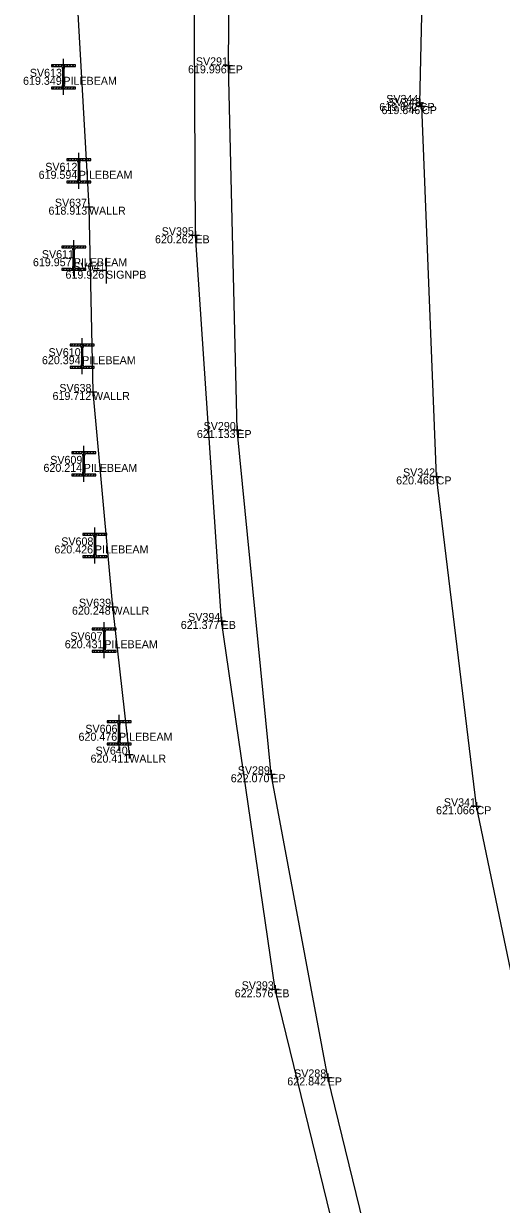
# Model space of a CAD drawing. Extents: x -2 to 1979875, y -2 to 232027.
# Drawn here: x 1978723.2 to 1978753, y 230727.4 to 230801.2 of the extents above; entities that cross this region are included whole.
import ezdxf

# ---------------------------------------------------------------- set-up
doc = ezdxf.new("R2010")
doc.units = 0
for name, color, linetype in [('_CIVIL_CONSTRUCTION', 7, 'Continuous'), ('GE_X_Alignment', 7, 'Continuous'), ('GE_X_Alignment_1000_Curve_Data', 7, 'Continuous'), ('GE_X_Alignment_1000_Stations', 7, 'Continuous'), ('GE_X_Alignment_100_Curve_Data', 7, 'Continuous'), ('GE_X_Alignment_100_Stations', 7, 'Continuous'), ('GE_X_Alignment_500_Stations', 7, 'Continuous'), ('GT_X_Piling_Cells', 7, 'Continuous'), ('RD_X_Wall', 7, 'Continuous'), ('SC_Scratch1', 7, 'Continuous')]:
    doc.layers.add(name, color=color, linetype=linetype)

msp = doc.modelspace()

# ---------------------------------------------------------------- linework, layer by layer
at = {"layer": 'GE_X_Alignment_1000_Curve_Data'}
msp.add_lwpolyline([(1978771.368, 230686.901), (1978762.945, 230707.808), (1978756.184, 230729.845), (1978751.49, 230752.309), (1978748.994, 230772.916), (1978748.08, 230796.049), (1978747.937, 230796.247), (1978748.471, 230819.071), (1978749.254, 230839.296), (1978750.532, 230861.092), (1978751.977, 230883.907), (1978753.538, 230907.259), (1978755.272, 230931.005), (1978756.708, 230952.708), (1978758.182, 230974.871), (1978759.598, 230998.872), (1978761.121, 231023.464)], dxfattribs=at)
at = {"layer": 'GE_X_Alignment_1000_Stations'}
msp.add_lwpolyline([(1978772.336, 230656.843), (1978763.559, 230673.456), (1978754.964, 230693.186), (1978747.098, 230715.323), (1978742.189, 230735.369), (1978738.656, 230754.308), (1978736.533, 230775.816), (1978735.988, 230798.596), (1978736.151, 230819.454), (1978737.13, 230840.16), (1978738.357, 230863.144), (1978739.649, 230887.098), (1978741.331, 230908.702), (1978742.827, 230930.869), (1978744.275, 230952.773), (1978745.794, 230976.041), (1978747.11, 230998.611), (1978748.464, 231019.612), (1978749.988, 231043.472)], dxfattribs=at)
at = {"layer": 'GE_X_Alignment_100_Curve_Data'}
for p, q in [((1978735.988, 230798.846), (1978735.988, 230798.346)), ((1978735.738, 230798.596), (1978736.238, 230798.596)), ((1978735.988, 230798.596), (1978735.988, 230798.596)), ((1978747.687, 230796.247), (1978748.187, 230796.247)), ((1978747.83, 230796.049), (1978748.33, 230796.049)), ((1978747.937, 230796.497), (1978747.937, 230795.997)), ((1978747.937, 230796.247), (1978747.937, 230796.247)), ((1978748.08, 230796.299), (1978748.08, 230795.799)), ((1978748.08, 230796.049), (1978748.08, 230796.049)), ((1978727.259, 230790.017), (1978727.259, 230789.517)), ((1978727.009, 230789.767), (1978727.509, 230789.767)), ((1978727.259, 230789.767), (1978727.259, 230789.767)), ((1978733.668, 230787.98), (1978734.168, 230787.98)), ((1978733.918, 230788.23), (1978733.918, 230787.73)), ((1978733.918, 230787.98), (1978733.918, 230787.98)), ((1978727.265, 230778.19), (1978727.765, 230778.19)), ((1978727.515, 230778.44), (1978727.515, 230777.94)), ((1978727.515, 230778.19), (1978727.515, 230778.19)), ((1978736.533, 230776.066), (1978736.533, 230775.566)), ((1978736.283, 230775.816), (1978736.783, 230775.816)), ((1978736.533, 230775.816), (1978736.533, 230775.816)), ((1978748.744, 230772.916), (1978749.244, 230772.916)), ((1978748.994, 230773.166), (1978748.994, 230772.666)), ((1978748.994, 230772.916), (1978748.994, 230772.916)), ((1978728.731, 230765.027), (1978728.731, 230764.527)), ((1978728.481, 230764.777), (1978728.981, 230764.777)), ((1978728.731, 230764.777), (1978728.731, 230764.777)), ((1978735.553, 230764.136), (1978735.553, 230763.636)), ((1978735.303, 230763.886), (1978735.803, 230763.886)), ((1978735.553, 230763.886), (1978735.553, 230763.886)), ((1978729.53, 230755.535), (1978730.03, 230755.535)), ((1978729.78, 230755.785), (1978729.78, 230755.285)), ((1978729.78, 230755.535), (1978729.78, 230755.535)), ((1978738.656, 230754.558), (1978738.656, 230754.058)), ((1978738.406, 230754.308), (1978738.906, 230754.308)), ((1978738.656, 230754.308), (1978738.656, 230754.308)), ((1978751.24, 230752.309), (1978751.74, 230752.309)), ((1978751.49, 230752.559), (1978751.49, 230752.059)), ((1978751.49, 230752.309), (1978751.49, 230752.309)), ((1978738.655, 230740.874), (1978739.155, 230740.874)), ((1978738.905, 230741.124), (1978738.905, 230740.624)), ((1978738.905, 230740.874), (1978738.905, 230740.874)), ((1978741.939, 230735.369), (1978742.439, 230735.369)), ((1978742.189, 230735.619), (1978742.189, 230735.119)), ((1978742.189, 230735.369), (1978742.189, 230735.369))]:
    msp.add_line(p, q, dxfattribs=at)
at = {"layer": 'GE_X_Alignment_500_Stations'}
for p, q in [((1978728.328, 230786.57), (1978728.328, 230784.97)), ((1978728.328, 230785.77), (1978727.528, 230785.77))]:
    msp.add_line(p, q, dxfattribs=at)
at = {"layer": 'GT_X_Piling_Cells'}
for p, q in [((1978725.664, 230796.755), (1978725.664, 230799.005)), ((1978726.414, 230798.63), (1978724.914, 230798.63)), ((1978724.914, 230798.63), (1978724.914, 230798.53)), ((1978724.914, 230798.53), (1978725.489, 230798.53)), ((1978724.977, 230798.53), (1978725.077, 230798.63)), ((1978725.153, 230798.53), (1978725.253, 230798.63)), ((1978725.33, 230798.53), (1978725.43, 230798.63)), ((1978725.506, 230798.529), (1978725.607, 230798.63)), ((1978725.605, 230798.451), (1978725.784, 230798.63)), ((1978725.614, 230798.405), (1978725.614, 230797.355)), ((1978725.614, 230798.284), (1978725.714, 230798.384)), ((1978725.614, 230798.107), (1978725.714, 230798.207)), ((1978725.614, 230797.93), (1978725.714, 230798.03)), ((1978725.714, 230797.355), (1978725.714, 230798.405)), ((1978725.839, 230798.53), (1978726.414, 230798.53)), ((1978725.86, 230798.53), (1978725.96, 230798.63)), ((1978726.037, 230798.53), (1978726.137, 230798.63)), ((1978726.214, 230798.53), (1978726.314, 230798.63)), ((1978726.391, 230798.53), (1978726.414, 230798.553)), ((1978726.414, 230798.53), (1978726.414, 230798.63)), ((1978725.521, 230797.13), (1978725.717, 230797.326)), ((1978725.614, 230797.753), (1978725.714, 230797.853)), ((1978725.614, 230797.576), (1978725.714, 230797.676)), ((1978725.614, 230797.4), (1978725.714, 230797.5)), ((1978725.664, 230797.88), (1978725.664, 230797.88)), ((1978725.489, 230797.23), (1978724.914, 230797.23)), ((1978724.914, 230797.23), (1978724.914, 230797.13)), ((1978724.914, 230797.13), (1978726.414, 230797.13)), ((1978724.991, 230797.13), (1978725.091, 230797.23)), ((1978725.168, 230797.13), (1978725.268, 230797.23)), ((1978725.344, 230797.13), (1978725.444, 230797.23)), ((1978725.698, 230797.13), (1978725.803, 230797.235)), ((1978726.414, 230797.23), (1978725.839, 230797.23)), ((1978725.875, 230797.13), (1978725.975, 230797.23)), ((1978726.051, 230797.13), (1978726.151, 230797.23)), ((1978726.228, 230797.13), (1978726.328, 230797.23)), ((1978726.405, 230797.13), (1978726.414, 230797.139)), ((1978726.414, 230797.13), (1978726.414, 230797.23)), ((1978726.633, 230790.882), (1978726.633, 230793.132)), ((1978727.383, 230792.757), (1978725.883, 230792.757)), ((1978725.883, 230792.757), (1978725.883, 230792.657)), ((1978725.883, 230792.657), (1978726.458, 230792.657)), ((1978725.946, 230792.657), (1978726.046, 230792.757)), ((1978726.122, 230792.657), (1978726.222, 230792.757)), ((1978726.299, 230792.657), (1978726.399, 230792.757)), ((1978726.475, 230792.656), (1978726.576, 230792.757)), ((1978726.574, 230792.578), (1978726.753, 230792.757)), ((1978726.583, 230792.532), (1978726.583, 230791.482)), ((1978726.583, 230792.411), (1978726.683, 230792.511)), ((1978726.583, 230792.234), (1978726.683, 230792.334)), ((1978726.583, 230792.057), (1978726.683, 230792.157)), ((1978726.683, 230791.482), (1978726.683, 230792.532)), ((1978726.808, 230792.657), (1978727.383, 230792.657)), ((1978726.829, 230792.657), (1978726.929, 230792.757)), ((1978727.006, 230792.657), (1978727.106, 230792.757)), ((1978727.183, 230792.657), (1978727.283, 230792.757)), ((1978727.36, 230792.657), (1978727.383, 230792.68)), ((1978727.383, 230792.657), (1978727.383, 230792.757)), ((1978726.458, 230791.357), (1978725.883, 230791.357)), ((1978725.883, 230791.357), (1978725.883, 230791.257)), ((1978725.96, 230791.257), (1978726.06, 230791.357)), ((1978726.137, 230791.257), (1978726.237, 230791.357)), ((1978726.313, 230791.257), (1978726.413, 230791.357)), ((1978726.49, 230791.257), (1978726.686, 230791.453)), ((1978726.583, 230791.88), (1978726.683, 230791.98)), ((1978726.583, 230791.703), (1978726.683, 230791.803)), ((1978726.583, 230791.527), (1978726.683, 230791.627)), ((1978726.633, 230792.007), (1978726.633, 230792.007)), ((1978726.667, 230791.257), (1978726.772, 230791.362)), ((1978727.383, 230791.357), (1978726.808, 230791.357)), ((1978726.844, 230791.257), (1978726.944, 230791.357)), ((1978727.02, 230791.257), (1978727.12, 230791.357)), ((1978727.197, 230791.257), (1978727.297, 230791.357)), ((1978727.383, 230791.257), (1978727.383, 230791.357)), ((1978725.883, 230791.257), (1978727.383, 230791.257)), ((1978727.374, 230791.257), (1978727.383, 230791.266)), ((1978726.311, 230785.423), (1978726.311, 230787.673)), ((1978727.061, 230787.298), (1978725.561, 230787.298)), ((1978725.561, 230787.298), (1978725.561, 230787.198)), ((1978725.561, 230787.198), (1978726.136, 230787.198)), ((1978725.624, 230787.198), (1978725.724, 230787.298)), ((1978725.8, 230787.198), (1978725.9, 230787.298)), ((1978725.977, 230787.198), (1978726.077, 230787.298)), ((1978726.153, 230787.197), (1978726.254, 230787.298)), ((1978726.252, 230787.119), (1978726.431, 230787.298)), ((1978726.261, 230787.073), (1978726.261, 230786.023)), ((1978726.261, 230786.952), (1978726.361, 230787.052)), ((1978726.361, 230786.023), (1978726.361, 230787.073)), ((1978726.486, 230787.198), (1978727.061, 230787.198)), ((1978726.507, 230787.198), (1978726.607, 230787.298)), ((1978726.684, 230787.198), (1978726.784, 230787.298)), ((1978726.861, 230787.198), (1978726.961, 230787.298)), ((1978727.038, 230787.198), (1978727.061, 230787.221)), ((1978727.061, 230787.198), (1978727.061, 230787.298)), ((1978726.261, 230786.775), (1978726.361, 230786.875)), ((1978726.261, 230786.598), (1978726.361, 230786.698)), ((1978726.261, 230786.421), (1978726.361, 230786.521)), ((1978726.261, 230786.244), (1978726.361, 230786.344)), ((1978726.311, 230786.548), (1978726.311, 230786.548)), ((1978726.136, 230785.898), (1978725.561, 230785.898)), ((1978725.561, 230785.898), (1978725.561, 230785.798)), ((1978725.561, 230785.798), (1978727.061, 230785.798)), ((1978725.638, 230785.798), (1978725.738, 230785.898)), ((1978725.815, 230785.798), (1978725.915, 230785.898)), ((1978725.991, 230785.798), (1978726.091, 230785.898)), ((1978726.168, 230785.798), (1978726.364, 230785.994)), ((1978726.261, 230786.068), (1978726.361, 230786.168)), ((1978726.345, 230785.798), (1978726.45, 230785.903)), ((1978727.061, 230785.898), (1978726.486, 230785.898)), ((1978726.522, 230785.798), (1978726.622, 230785.898)), ((1978726.698, 230785.798), (1978726.798, 230785.898)), ((1978726.875, 230785.798), (1978726.975, 230785.898)), ((1978727.052, 230785.798), (1978727.061, 230785.807)), ((1978727.061, 230785.798), (1978727.061, 230785.898)), ((1978727.59, 230781.176), (1978726.09, 230781.176)), ((1978726.09, 230781.176), (1978726.09, 230781.076)), ((1978726.09, 230781.076), (1978726.665, 230781.076)), ((1978726.153, 230781.076), (1978726.253, 230781.176)), ((1978726.329, 230781.076), (1978726.429, 230781.176)), ((1978726.506, 230781.076), (1978726.606, 230781.176)), ((1978726.682, 230781.075), (1978726.783, 230781.176)), ((1978726.781, 230780.997), (1978726.96, 230781.176)), ((1978726.84, 230779.301), (1978726.84, 230781.551)), ((1978727.015, 230781.076), (1978727.59, 230781.076)), ((1978727.036, 230781.076), (1978727.136, 230781.176)), ((1978727.213, 230781.076), (1978727.313, 230781.176)), ((1978727.39, 230781.076), (1978727.49, 230781.176)), ((1978727.567, 230781.076), (1978727.59, 230781.099)), ((1978727.59, 230781.076), (1978727.59, 230781.176)), ((1978726.79, 230780.951), (1978726.79, 230779.901)), ((1978726.79, 230780.83), (1978726.89, 230780.93)), ((1978726.79, 230780.653), (1978726.89, 230780.753)), ((1978726.79, 230780.476), (1978726.89, 230780.576)), ((1978726.79, 230780.299), (1978726.89, 230780.399)), ((1978726.84, 230780.426), (1978726.84, 230780.426)), ((1978726.89, 230779.901), (1978726.89, 230780.951)), ((1978726.665, 230779.776), (1978726.09, 230779.776)), ((1978726.09, 230779.776), (1978726.09, 230779.676)), ((1978726.09, 230779.676), (1978727.59, 230779.676)), ((1978726.167, 230779.676), (1978726.267, 230779.776)), ((1978726.344, 230779.676), (1978726.444, 230779.776)), ((1978726.52, 230779.676), (1978726.62, 230779.776)), ((1978726.697, 230779.676), (1978726.893, 230779.872)), ((1978726.79, 230780.122), (1978726.89, 230780.222)), ((1978726.79, 230779.946), (1978726.89, 230780.046)), ((1978726.874, 230779.676), (1978726.979, 230779.781)), ((1978727.59, 230779.776), (1978727.015, 230779.776)), ((1978727.051, 230779.676), (1978727.151, 230779.776)), ((1978727.227, 230779.676), (1978727.327, 230779.776)), ((1978727.404, 230779.676), (1978727.504, 230779.776)), ((1978727.581, 230779.676), (1978727.59, 230779.685)), ((1978727.59, 230779.676), (1978727.59, 230779.776)), ((1978727.685, 230774.449), (1978726.185, 230774.449)), ((1978726.185, 230774.449), (1978726.185, 230774.349)), ((1978726.248, 230774.349), (1978726.348, 230774.449)), ((1978726.424, 230774.349), (1978726.524, 230774.449)), ((1978726.601, 230774.349), (1978726.701, 230774.449)), ((1978726.777, 230774.348), (1978726.878, 230774.449)), ((1978726.876, 230774.27), (1978727.055, 230774.449)), ((1978726.935, 230772.574), (1978726.935, 230774.824)), ((1978727.131, 230774.349), (1978727.231, 230774.449)), ((1978727.308, 230774.349), (1978727.408, 230774.449)), ((1978727.485, 230774.349), (1978727.585, 230774.449)), ((1978727.685, 230774.349), (1978727.685, 230774.449)), ((1978726.185, 230774.349), (1978726.76, 230774.349)), ((1978726.885, 230774.224), (1978726.885, 230773.174)), ((1978726.885, 230774.103), (1978726.985, 230774.203)), ((1978726.885, 230773.926), (1978726.985, 230774.026)), ((1978726.885, 230773.749), (1978726.985, 230773.849)), ((1978726.885, 230773.572), (1978726.985, 230773.672)), ((1978726.935, 230773.699), (1978726.935, 230773.699)), ((1978726.985, 230773.174), (1978726.985, 230774.224)), ((1978727.11, 230774.349), (1978727.685, 230774.349)), ((1978727.662, 230774.349), (1978727.685, 230774.372)), ((1978726.76, 230773.049), (1978726.185, 230773.049)), ((1978726.185, 230773.049), (1978726.185, 230772.949)), ((1978726.185, 230772.949), (1978727.685, 230772.949)), ((1978726.262, 230772.949), (1978726.362, 230773.049)), ((1978726.439, 230772.949), (1978726.539, 230773.049)), ((1978726.615, 230772.949), (1978726.715, 230773.049)), ((1978726.792, 230772.949), (1978726.988, 230773.145)), ((1978726.885, 230773.395), (1978726.985, 230773.495)), ((1978726.885, 230773.219), (1978726.985, 230773.319)), ((1978726.969, 230772.949), (1978727.074, 230773.054)), ((1978727.685, 230773.049), (1978727.11, 230773.049)), ((1978727.146, 230772.949), (1978727.246, 230773.049)), ((1978727.322, 230772.949), (1978727.422, 230773.049)), ((1978727.499, 230772.949), (1978727.599, 230773.049)), ((1978727.676, 230772.949), (1978727.685, 230772.958)), ((1978727.685, 230772.949), (1978727.685, 230773.049)), ((1978728.384, 230769.354), (1978726.884, 230769.354)), ((1978726.884, 230769.354), (1978726.884, 230769.254)), ((1978726.884, 230769.254), (1978727.459, 230769.254)), ((1978726.947, 230769.254), (1978727.047, 230769.354)), ((1978727.123, 230769.254), (1978727.223, 230769.354)), ((1978727.3, 230769.254), (1978727.4, 230769.354)), ((1978727.476, 230769.253), (1978727.577, 230769.354)), ((1978727.575, 230769.175), (1978727.754, 230769.354)), ((1978727.634, 230767.479), (1978727.634, 230769.729)), ((1978727.809, 230769.254), (1978728.384, 230769.254)), ((1978727.83, 230769.254), (1978727.93, 230769.354)), ((1978728.007, 230769.254), (1978728.107, 230769.354)), ((1978728.184, 230769.254), (1978728.284, 230769.354)), ((1978728.361, 230769.254), (1978728.384, 230769.277)), ((1978728.384, 230769.254), (1978728.384, 230769.354)), ((1978727.584, 230769.129), (1978727.584, 230768.079)), ((1978727.584, 230769.008), (1978727.684, 230769.108)), ((1978727.584, 230768.831), (1978727.684, 230768.931)), ((1978727.584, 230768.654), (1978727.684, 230768.754)), ((1978727.584, 230768.477), (1978727.684, 230768.577)), ((1978727.634, 230768.604), (1978727.634, 230768.604)), ((1978727.684, 230768.079), (1978727.684, 230769.129)), ((1978727.459, 230767.954), (1978726.884, 230767.954)), ((1978726.884, 230767.954), (1978726.884, 230767.854)), ((1978726.884, 230767.854), (1978728.384, 230767.854)), ((1978726.961, 230767.854), (1978727.061, 230767.954)), ((1978727.138, 230767.854), (1978727.238, 230767.954)), ((1978727.314, 230767.854), (1978727.414, 230767.954)), ((1978727.491, 230767.854), (1978727.687, 230768.05)), ((1978727.584, 230768.3), (1978727.684, 230768.4)), ((1978727.584, 230768.124), (1978727.684, 230768.224)), ((1978727.668, 230767.854), (1978727.773, 230767.959)), ((1978728.384, 230767.954), (1978727.809, 230767.954)), ((1978727.845, 230767.854), (1978727.945, 230767.954)), ((1978728.021, 230767.854), (1978728.121, 230767.954)), ((1978728.198, 230767.854), (1978728.298, 230767.954)), ((1978728.375, 230767.854), (1978728.384, 230767.863)), ((1978728.384, 230767.854), (1978728.384, 230767.954)), ((1978728.973, 230763.431), (1978727.473, 230763.431)), ((1978727.473, 230763.431), (1978727.473, 230763.331)), ((1978727.473, 230763.331), (1978728.048, 230763.331)), ((1978727.536, 230763.331), (1978727.636, 230763.431)), ((1978727.712, 230763.331), (1978727.812, 230763.431)), ((1978727.889, 230763.331), (1978727.989, 230763.431)), ((1978728.065, 230763.33), (1978728.166, 230763.431)), ((1978728.164, 230763.252), (1978728.343, 230763.431)), ((1978728.223, 230761.556), (1978728.223, 230763.806)), ((1978728.398, 230763.331), (1978728.973, 230763.331)), ((1978728.419, 230763.331), (1978728.519, 230763.431)), ((1978728.596, 230763.331), (1978728.696, 230763.431)), ((1978728.773, 230763.331), (1978728.873, 230763.431)), ((1978728.95, 230763.331), (1978728.973, 230763.354)), ((1978728.973, 230763.331), (1978728.973, 230763.431)), ((1978728.173, 230763.206), (1978728.173, 230762.156)), ((1978728.173, 230763.085), (1978728.273, 230763.185)), ((1978728.173, 230762.908), (1978728.273, 230763.008)), ((1978728.173, 230762.731), (1978728.273, 230762.831)), ((1978728.173, 230762.554), (1978728.273, 230762.654)), ((1978728.223, 230762.681), (1978728.223, 230762.681)), ((1978728.273, 230762.156), (1978728.273, 230763.206)), ((1978728.048, 230762.031), (1978727.473, 230762.031)), ((1978727.473, 230762.031), (1978727.473, 230761.931)), ((1978727.473, 230761.931), (1978728.973, 230761.931)), ((1978727.55, 230761.931), (1978727.65, 230762.031)), ((1978727.727, 230761.931), (1978727.827, 230762.031)), ((1978727.903, 230761.931), (1978728.003, 230762.031)), ((1978728.08, 230761.931), (1978728.276, 230762.127)), ((1978728.173, 230762.377), (1978728.273, 230762.477)), ((1978728.173, 230762.201), (1978728.273, 230762.301)), ((1978728.257, 230761.931), (1978728.362, 230762.036)), ((1978728.973, 230762.031), (1978728.398, 230762.031)), ((1978728.434, 230761.931), (1978728.534, 230762.031)), ((1978728.61, 230761.931), (1978728.71, 230762.031)), ((1978728.787, 230761.931), (1978728.887, 230762.031)), ((1978728.964, 230761.931), (1978728.973, 230761.94)), ((1978728.973, 230761.931), (1978728.973, 230762.031)), ((1978729.892, 230757.65), (1978728.392, 230757.65)), ((1978728.392, 230757.65), (1978728.392, 230757.55)), ((1978728.392, 230757.55), (1978728.967, 230757.55)), ((1978728.455, 230757.55), (1978728.555, 230757.65)), ((1978728.631, 230757.55), (1978728.731, 230757.65)), ((1978728.808, 230757.55), (1978728.908, 230757.65)), ((1978728.984, 230757.549), (1978729.085, 230757.65)), ((1978729.083, 230757.471), (1978729.262, 230757.65)), ((1978729.092, 230757.425), (1978729.092, 230756.375)), ((1978729.142, 230755.775), (1978729.142, 230758.025)), ((1978729.192, 230756.375), (1978729.192, 230757.425)), ((1978729.317, 230757.55), (1978729.892, 230757.55)), ((1978729.338, 230757.55), (1978729.438, 230757.65)), ((1978729.515, 230757.55), (1978729.615, 230757.65)), ((1978729.692, 230757.55), (1978729.792, 230757.65)), ((1978729.869, 230757.55), (1978729.892, 230757.573)), ((1978729.892, 230757.55), (1978729.892, 230757.65)), ((1978729.092, 230757.304), (1978729.192, 230757.404)), ((1978729.092, 230757.127), (1978729.192, 230757.227)), ((1978729.092, 230756.95), (1978729.192, 230757.05)), ((1978729.092, 230756.773), (1978729.192, 230756.873)), ((1978729.092, 230756.596), (1978729.192, 230756.696)), ((1978729.142, 230756.9), (1978729.142, 230756.9)), ((1978728.967, 230756.25), (1978728.392, 230756.25)), ((1978728.392, 230756.25), (1978728.392, 230756.15)), ((1978728.392, 230756.15), (1978729.892, 230756.15)), ((1978728.469, 230756.15), (1978728.569, 230756.25)), ((1978728.646, 230756.15), (1978728.746, 230756.25)), ((1978728.822, 230756.15), (1978728.922, 230756.25)), ((1978728.999, 230756.15), (1978729.195, 230756.346)), ((1978729.092, 230756.42), (1978729.192, 230756.52)), ((1978729.176, 230756.15), (1978729.281, 230756.255)), ((1978729.892, 230756.25), (1978729.317, 230756.25)), ((1978729.353, 230756.15), (1978729.453, 230756.25)), ((1978729.529, 230756.15), (1978729.629, 230756.25)), ((1978729.706, 230756.15), (1978729.806, 230756.25)), ((1978729.883, 230756.15), (1978729.892, 230756.159)), ((1978729.892, 230756.15), (1978729.892, 230756.25))]:
    msp.add_line(p, q, dxfattribs=at)
for centre, start, end in [((1978725.489, 230798.405), 0, 90), ((1978725.839, 230798.405), 90, 180), ((1978725.489, 230797.355), 270, 0), ((1978725.839, 230797.355), 180, 270), ((1978726.458, 230792.532), 0, 90), ((1978726.808, 230792.532), 90, 180), ((1978726.458, 230791.482), 270, 0), ((1978726.808, 230791.482), 180, 270), ((1978726.136, 230787.073), 0, 90), ((1978726.486, 230787.073), 90, 180), ((1978726.136, 230786.023), 270, 0), ((1978726.486, 230786.023), 180, 270), ((1978726.665, 230780.951), 0, 90), ((1978727.015, 230780.951), 90, 180), ((1978726.665, 230779.901), 270, 0), ((1978727.015, 230779.901), 180, 270), ((1978726.76, 230774.224), 0, 90), ((1978727.11, 230774.224), 90, 180), ((1978726.76, 230773.174), 270, 0), ((1978727.11, 230773.174), 180, 270), ((1978727.459, 230769.129), 0, 90), ((1978727.809, 230769.129), 90, 180), ((1978727.459, 230768.079), 270, 0), ((1978727.809, 230768.079), 180, 270), ((1978728.048, 230763.206), 0, 90), ((1978728.398, 230763.206), 90, 180), ((1978728.048, 230762.156), 270, 0), ((1978728.398, 230762.156), 180, 270), ((1978728.967, 230757.425), 0, 90), ((1978729.317, 230757.425), 90, 180), ((1978728.967, 230756.375), 270, 0), ((1978729.317, 230756.375), 180, 270)]:
    msp.add_arc(centre, 0.125, start, end, dxfattribs=at)
at = {"layer": 'RD_X_Wall'}
msp.add_lwpolyline([(1978732.056, 230886.781), (1978731.746, 230883.073), (1978731.431, 230882.716), (1978730.487, 230868.646), (1978729.395, 230856.593), (1978727.895, 230838.391), (1978726.998, 230826.855), (1978726.244, 230816.011), (1978726.384, 230805.15), (1978727.259, 230789.767), (1978727.515, 230778.19), (1978728.731, 230764.777), (1978729.78, 230755.535)], dxfattribs=at)
at = {"layer": 'SC_Scratch1'}
msp.add_lwpolyline([(1978770.288, 230655.73), (1978760.891, 230674.584), (1978752.193, 230695.227), (1978744.942, 230716.175), (1978738.905, 230740.874), (1978735.553, 230763.886), (1978733.918, 230787.98), (1978733.819, 230809.219), (1978734.805, 230833.453), (1978736.148, 230858.007), (1978737.85, 230882.597), (1978739.105, 230905.756), (1978740.693, 230929.953), (1978742.419, 230953.633), (1978743.494, 230976.312), (1978745.216, 230999.029), (1978746.767, 231023.392)], dxfattribs=at)

# ---------------------------------------------------------------- texts
at = {"layer": '_CIVIL_CONSTRUCTION'}
for s, p in [('619.996', (1978733.456, 230798.096)), ('619.349', (1978723.143, 230797.38)), ('619.642', (1978745.409, 230795.747)), ('619.646', (1978745.548, 230795.549)), ('619.594', (1978724.117, 230791.507)), ('618.913', (1978724.734, 230789.267)), ('620.262', (1978731.39, 230787.48)), ('619.957', (1978723.76, 230786.048)), ('619.926', (1978725.796, 230785.27)), ('620.394', (1978724.324, 230779.926)), ('619.712', (1978724.987, 230777.69)), ('621.133', (1978734.008, 230775.316)), ('620.214', (1978724.419, 230773.199)), ('620.468', (1978746.464, 230772.416)), ('620.426', (1978725.102, 230768.104)), ('620.248', (1978726.201, 230764.277)), ('621.377', (1978733.002, 230763.386)), ('620.431', (1978725.753, 230762.181)), ('620.476', (1978726.61, 230756.4)), ('620.411', (1978727.362, 230755.035)), ('622.070', (1978736.126, 230753.808)), ('621.066', (1978748.958, 230751.809)), ('622.576', (1978736.373, 230740.374)), ('622.842', (1978739.661, 230734.869))]:
    msp.add_text(s, height=0.5, dxfattribs=at).set_placement(p)
at = {"layer": 'GE_X_Alignment'}
for s, p in [('SV291', (1978733.945, 230798.596)), ('SV613', (1978723.566, 230797.88)), ('SV344', (1978745.848, 230796.247)), ('SV343', (1978745.982, 230796.049)), ('SV612', (1978724.532, 230792.007)), ('SV637', (1978725.134, 230789.767)), ('SV395', (1978731.809, 230787.98)), ('SV611', (1978724.319, 230786.548)), ('SV641', (1978726.285, 230785.77)), ('SV610', (1978724.736, 230780.426)), ('SV638', (1978725.412, 230778.19)), ('SV290', (1978734.429, 230775.816)), ('SV609', (1978724.841, 230773.699)), ('SV342', (1978746.893, 230772.916)), ('SV608', (1978725.531, 230768.604)), ('SV639', (1978726.637, 230764.777)), ('SV394', (1978733.464, 230763.886)), ('SV607', (1978726.098, 230762.681)), ('SV606', (1978727.037, 230756.9)), ('SV640', (1978727.676, 230755.535)), ('SV289', (1978736.562, 230754.308)), ('SV341', (1978749.447, 230752.309)), ('SV393', (1978736.807, 230740.874)), ('SV288', (1978740.086, 230735.369))]:
    msp.add_text(s, height=0.5, dxfattribs=at).set_placement(p)
at = {"layer": 'GE_X_Alignment_100_Stations'}
for s, p in [('EP', (1978735.988, 230798.096)), ('PILEBEAM', (1978725.664, 230797.38)), ('CP', (1978747.937, 230795.747)), ('CP', (1978748.08, 230795.549)), ('PILEBEAM', (1978726.633, 230791.507)), ('WALLR', (1978727.259, 230789.267)), ('EB', (1978733.918, 230787.48)), ('PILEBEAM', (1978726.311, 230786.048)), ('SIGNPB', (1978728.328, 230785.27)), ('PILEBEAM', (1978726.84, 230779.926)), ('WALLR', (1978727.515, 230777.69)), ('EP', (1978736.533, 230775.316)), ('PILEBEAM', (1978726.935, 230773.199)), ('CP', (1978748.994, 230772.416)), ('PILEBEAM', (1978727.634, 230768.104)), ('WALLR', (1978728.731, 230764.277)), ('EB', (1978735.553, 230763.386)), ('PILEBEAM', (1978728.223, 230762.181)), ('PILEBEAM', (1978729.142, 230756.4)), ('WALLR', (1978729.78, 230755.035)), ('EP', (1978738.656, 230753.808)), ('CP', (1978751.49, 230751.809)), ('EB', (1978738.905, 230740.374)), ('EP', (1978742.189, 230734.869))]:
    msp.add_text(s, height=0.5, dxfattribs=at).set_placement(p)

doc.saveas('drawing.dxf')
